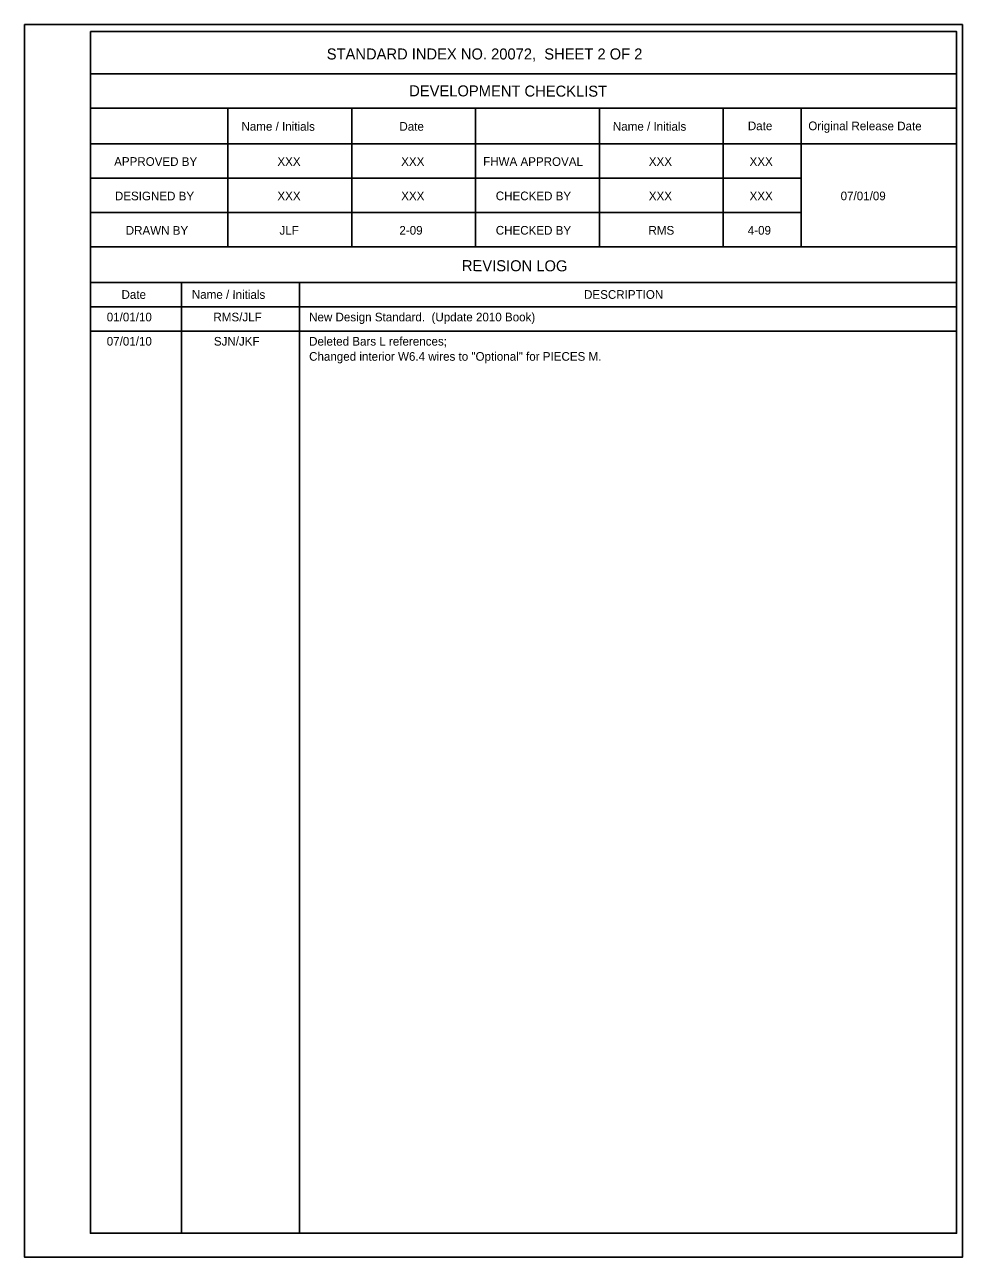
# Model space of a CAD drawing. Extents: x 4.6 to 40.7, y 0.2 to 17.4.
# Drawn here: x 29.79 to 40.7, y 2.25 to 16.59 of the extents above; entities that cross this region are included whole.
import ezdxf

# ---------------------------------------------------------------- set-up
doc = ezdxf.new("R2010")
doc.units = 0
for name, color, linetype in [('Border', 7, 'Continuous'), ('Dimension', 7, 'Continuous'), ('PlotBorder_dp', 7, 'Continuous'), ('TextStructures', 7, 'Continuous')]:
    doc.layers.add(name, color=color, linetype=linetype)

msp = doc.modelspace()

# ---------------------------------------------------------------- linework, layer by layer
at = {"layer": 'Border'}
for p, q in [((40.633, 16.015), (30.559, 16.015)), ((40.633, 15.615), (30.559, 15.615)), ((32.159, 15.615), (32.159, 14.002)), ((33.599, 15.615), (33.599, 14.002)), ((35.039, 15.615), (35.039, 14.002)), ((36.479, 15.615), (36.479, 14.002)), ((37.919, 15.615), (37.919, 14.002)), ((38.827, 15.615), (38.827, 14.002)), ((40.633, 15.202), (30.559, 15.202)), ((38.827, 14.802), (30.559, 14.802)), ((38.827, 14.402), (30.559, 14.402)), ((40.633, 14.002), (30.559, 14.002)), ((40.633, 13.588), (30.559, 13.588)), ((31.62, 13.588), (31.62, 2.534)), ((32.991, 13.588), (32.991, 2.534)), ((40.633, 13.306), (30.559, 13.306))]:
    msp.add_line(p, q, dxfattribs=at)
msp.add_lwpolyline([(30.56, 16.506), (40.633, 16.506), (40.633, 2.534), (30.56, 2.534)], close=True, dxfattribs=at)
at = {"layer": 'Dimension'}
msp.add_line((30.56, 13.024), (40.633, 13.024), dxfattribs=at)
at = {"layer": 'PlotBorder_dp'}
msp.add_line((29.794, 2.254), (29.794, 2.254), dxfattribs=at)
msp.add_lwpolyline([(29.794, 16.587), (40.701, 16.587), (40.701, 2.254), (29.794, 2.254)], close=True, dxfattribs=at)

# ---------------------------------------------------------------- texts
at = {"layer": 'TextStructures'}
for s, height, p in [('STANDARD INDEX NO. 20072,  SHEET 2 OF 2', 0.128, (33.308, 16.182)), ('XXX', 0.1008, (32.734, 14.945)), ('XXX', 0.1008, (34.174, 14.945)), ('XXX', 0.1008, (37.054, 14.945)), ('XXX', 0.1008, (38.226, 14.945)), ('XXX', 0.1008, (32.734, 14.545)), ('XXX', 0.1008, (34.174, 14.545)), ('XXX', 0.1008, (37.054, 14.545)), ('XXX', 0.1008, (38.226, 14.545)), ('07/01/09', 0.1008, (39.285, 14.545)), ('JLF', 0.1008, (32.759, 14.145)), ('2-09', 0.1008, (34.153, 14.145)), ('RMS', 0.1008, (37.05, 14.145)), ('4-09', 0.1008, (38.205, 14.145)), ('DESCRIPTION', 0.1008, (36.301, 13.399)), ('01/01/10', 0.1008, (30.749, 13.137)), ('RMS/JLF', 0.1008, (31.99, 13.137)), ('New Design Standard.  (Update 2010 Book)', 0.1008, (33.103, 13.137)), ('07/01/10', 0.1008, (30.749, 12.855)), ('SJN/JKF', 0.1008, (31.995, 12.855)), ('Deleted Bars L references;', 0.1008, (33.103, 12.855)), ('Changed interior W6.4 wires to "Optional" for PIECES M.', 0.1008, (33.103, 12.679))]:
    msp.add_text(s, height=height, dxfattribs=at).set_placement(p)
for s, height, p in [('DEVELOPMENT CHECKLIST', 0.128, (34.267, 15.754)), ('Name / Initials', 0.1008, (32.316, 15.355)), ('Date', 0.1008, (34.153, 15.354)), ('Name / Initials', 0.1008, (36.636, 15.355)), ('Date', 0.1008, (38.206, 15.36)), ('Original Release Date', 0.1008, (38.909, 15.36)), ('APPROVED BY', 0.1008, (30.835, 14.946)), ('FHWA APPROVAL', 0.1008, (35.127, 14.946)), ('DESIGNED BY', 0.1008, (30.844, 14.545)), ('CHECKED BY', 0.1008, (35.274, 14.546)), ('DRAWN BY', 0.1008, (30.97, 14.145)), ('CHECKED BY', 0.1008, (35.274, 14.146)), ('REVISION LOG', 0.128, (34.88, 13.721)), ('Date', 0.1008, (30.921, 13.399)), ('Name / Initials', 0.1008, (31.739, 13.4))]:
    msp.add_text(s, height=height, rotation=359.8756, dxfattribs=at).set_placement(p)

doc.saveas('drawing.dxf')
